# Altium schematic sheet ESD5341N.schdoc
size 127 x 101 mm
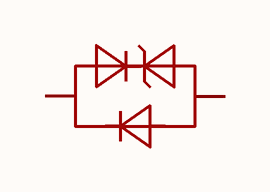
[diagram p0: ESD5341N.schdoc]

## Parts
U?  esd5341n  [DFN1006-2L-RD]  (value not drawn)

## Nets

Not connected (* = marked no-connect by the designer): U? 1 2

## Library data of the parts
U? = esd5341n: 极性:单向;反向截止电压(Vrwm):5V;最大钳位电压:20V;峰值脉冲电流(Ipp):3.3A;峰值脉冲功率(Ppp):70W;击穿电压:6V;; Manufacturer: TECH PUBLIC(台舟); AddInBom: yes; ModelId: 96b2cca1435e47b08b55ab6e73617580; ModelName: DFN1006_L1-W0.6-H0.4-2L-RD; ModelTransform: 40.1574,24.4094,0,0,0,0,0,0,0; polarity: 单向; Reverse Stand-Off Voltage (Vrwm): 5V; Maximum Clamping Voltage: 20V; Peak Pulse Current (Ipp): 3.3A; Peak Pulse Power Dissipation (Ppp): 70W; Breakdown Voltage: 6V; Reverse Leakage Current (Ir): 80nA; Number of Lines: 单路; level of protection: IEC 61000-4-2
